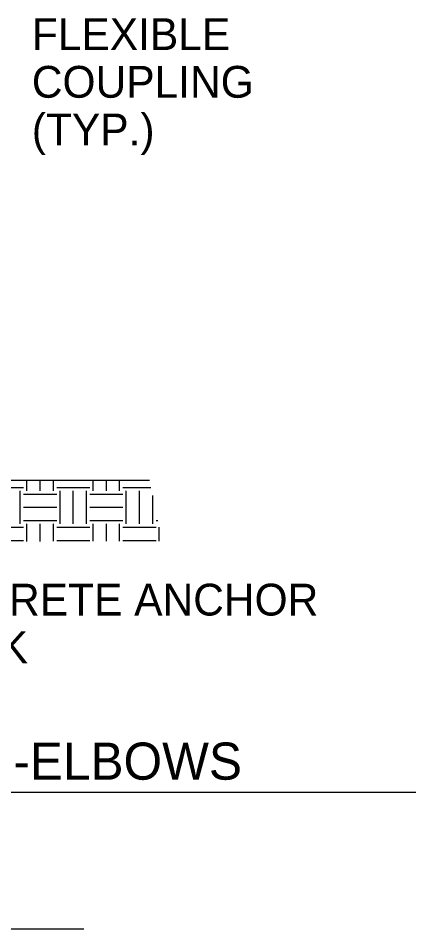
# Model space of a CAD drawing. Extents: x 9999.96 to 10005.26, y 9999.88 to 10002.38.
# Drawn here: x 10001.4258 to 10001.5509, y 10000.4835 to 10000.7698 of the extents above; entities that cross this region are included whole.
import ezdxf

# ---------------------------------------------------------------- set-up
doc = ezdxf.new("R2010")
doc.units = 0
doc.layers.add('Level 2', color=7, linetype='Continuous')

msp = doc.modelspace()

# ---------------------------------------------------------------- linework, layer by layer
at = {"layer": 'Level 2'}
for p, q in [((10001.215, 10000.62455), (10001.4671, 10000.62455)), ((10001.42854, 10000.62126), (10001.42854, 10000.62469)), ((10001.43271, 10000.62126), (10001.43271, 10000.62469)), ((10001.43688, 10000.62126), (10001.43688, 10000.62469)), ((10001.44938, 10000.62126), (10001.44938, 10000.62469)), ((10001.45354, 10000.62126), (10001.45354, 10000.62469)), ((10001.45771, 10000.62126), (10001.45771, 10000.62469)), ((10001.41708, 10000.6223), (10001.4275, 10000.6223)), ((10001.42646, 10000.61084), (10001.42646, 10000.62126)), ((10001.4275, 10000.62022), (10001.43792, 10000.62022)), ((10001.43792, 10000.6223), (10001.44833, 10000.6223)), ((10001.43896, 10000.61084), (10001.43896, 10000.62126)), ((10001.44313, 10000.61084), (10001.44313, 10000.62126)), ((10001.44729, 10000.61084), (10001.44729, 10000.62126)), ((10001.44833, 10000.62022), (10001.45875, 10000.62022)), ((10001.45875, 10000.6223), (10001.46758, 10000.6223)), ((10001.45979, 10000.61084), (10001.45979, 10000.62126)), ((10001.46396, 10000.61084), (10001.46396, 10000.62126)), ((10001.46813, 10000.61084), (10001.46813, 10000.61972)), ((10001.4275, 10000.61605), (10001.43792, 10000.61605)), ((10001.44833, 10000.61605), (10001.45875, 10000.61605)), ((10001.4275, 10000.61189), (10001.43792, 10000.61189)), ((10001.44833, 10000.61189), (10001.45875, 10000.61189)), ((10001.46917, 10000.61189), (10001.46978, 10000.61189)), ((10001.41708, 10000.6098), (10001.4275, 10000.6098)), ((10001.42854, 10000.60532), (10001.42854, 10000.61084)), ((10001.43271, 10000.60533), (10001.43271, 10000.61084)), ((10001.43688, 10000.60535), (10001.43688, 10000.61084)), ((10001.43792, 10000.6098), (10001.44833, 10000.6098)), ((10001.44938, 10000.60539), (10001.44938, 10000.61084)), ((10001.45354, 10000.6054), (10001.45354, 10000.61084)), ((10001.45771, 10000.60542), (10001.45771, 10000.61084)), ((10001.45875, 10000.6098), (10001.46917, 10000.6098)), ((10001.47021, 10000.60545), (10001.47021, 10000.60985)), ((10001.41708, 10000.60564), (10001.4275, 10000.60564)), ((10001.43792, 10000.60564), (10001.44833, 10000.60564)), ((10001.45875, 10000.60564), (10001.46917, 10000.60564)), ((10001.18141, 10000.52653), (10001.55093, 10000.52653)), ((10001.29469, 10000.48353), (10001.44647, 10000.48353))]:
    msp.add_line(p, q, dxfattribs=at)

# ---------------------------------------------------------------- texts
for s, height, p in [('FLEXIBLE', 0.01, (10001.43009, 10000.75981)), ('COUPLING', 0.01, (10001.43009, 10000.74481)), ('(TYP.)', 0.01, (10001.43009, 10000.72981)), ('CONCRETE ANCHOR', 0.01, (10001.38355, 10000.58202)), ('BLOCK', 0.01, (10001.38355, 10000.56702)), ('UNDERGROUND PIPING RISER-ELBOWS', 0.0116667, (10001.19024, 10000.53041))]:
    msp.add_text(s, height=height, dxfattribs=at).set_placement(p)

doc.saveas('drawing.dxf')
